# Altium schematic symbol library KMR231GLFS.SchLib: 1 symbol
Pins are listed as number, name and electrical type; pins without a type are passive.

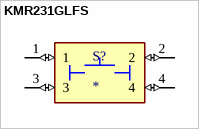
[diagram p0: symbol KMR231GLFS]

## KMR231GLFS
designator S?
Tactile Switch SPST-NO Top Actuated Surface Mount; MP: KMR231GLFS; MF: C&K
footprint KMR231GLFS
pins: 1 (io), 2 (io), 3 (io), 4 (io)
